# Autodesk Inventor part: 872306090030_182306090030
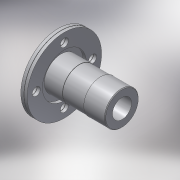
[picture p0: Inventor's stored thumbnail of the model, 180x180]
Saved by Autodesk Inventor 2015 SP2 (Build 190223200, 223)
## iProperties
Created: 2017-02
Part Number: 872306090030_182306090030
Material: PVC-Piping
Description: PLASSON FLANGE ADAPTOR WITH METAL FLANGE 90-3"
Document SubType Name: Modeling
Designer: KIM
Mass: 92.6774 g
Surface Area: 199.44 cm^2
Volume: 66.1981 cm^3
Density: 1.4 g/cm^3
Appearance: Smooth - White
Author: Кирилл
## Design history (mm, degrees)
derived "872306.ipt"
feature "Solid1::872306.ipt"
tag "TaggingFeature1"
body "Solid1"
other parameters: "d73" = 17.5, "d74" = 90 deg, "d75" = 0.3, "d77" = 18, "d80" = 0, "d82" = 360 deg, "d96" = 0.3, "d99" = 360 deg, "d103" = 175, "d104" = 1.8, "d107" = 117, "d108" = 4.375, "d116" = 88.2, "d117" = 58.33333, "d118" = 58.33333, "d120" = 4.5, "H_" = 175, "S_" = 18
